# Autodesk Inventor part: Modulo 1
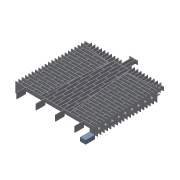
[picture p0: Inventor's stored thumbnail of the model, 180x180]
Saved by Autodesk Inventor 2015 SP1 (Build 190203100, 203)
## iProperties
Created: 2015-04
Part Number: Modulo 1
Material: Generic
Document SubType Name: Modeling
Designer: treina2
Density: 1 g/cm^3
Appearance: Default
Author: treina2
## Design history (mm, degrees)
sketch "Sketch1"
  geometry: L1 (1091.806, 200)-(1091.806, 440) reference; L2 (1091.806, 440)-(1033.806, 440) reference; L3 (1033.806, 440)-(1033.806, 200) reference; L4 (1033.806, 200)-(1091.806, 200) reference; L5 (1159.806, 200)-(1159.806, 315) reference; L6 (1159.806, 315)-(1101.806, 315) reference; L7 (1101.806, 315)-(1101.806, 200) reference; L8 (1101.806, 200)-(1159.806, 200) reference; L9 (1227.806, 200)-(1227.806, 440) reference; L10 (1227.806, 440)-(1169.806, 440) reference; L11 (1169.806, 440)-(1169.806, 200) reference; L12 (1169.806, 200)-(1227.806, 200) reference; L13 (1024, 200)-(1024, 315) reference; L14 (1024, 315)-(966, 315) reference; L15 (966, 315)-(966, 200) reference; L16 (966, 200)-(1024, 200) reference; L17 (1169.806, 1464.632)-(1169.806, 1450) reference; L18 (1169.806, 1450)-(1171.263, 1450) reference; L19 (1284.348, 315)-(1237.806, 315) reference; L20 (1237.806, 315)-(1237.806, 200) reference; L21 (1237.806, 200)-(1295.806, 200) reference; L22 (1259.439, 565)-(1283.351, 325) reference; L23 (1259.439, 565)-(1237.806, 565) reference; L24 (1237.806, 565)-(1237.806, 325) reference; L25 (1237.806, 325)-(1283.351, 325) reference; L26 (1169.806, 1565)-(1177.128, 1492) reference; L27 (1237.806, 1498.938)-(1295.806, 1505.57) reference; L28 (1295.806, 1505.57)-(1295.806, 1686) reference; L29 (1295.806, 1686)-(1237.806, 1686) reference; L30 (1237.806, 1686)-(1237.806, 1498.938) reference; L31 (1159.806, 325)-(1159.806, 565) reference; L32 (1159.806, 565)-(1101.806, 565) reference; L33 (1101.806, 565)-(1101.806, 325) reference; L34 (1101.806, 325)-(1159.806, 325) reference; L35 (1703.806, 1552.224)-(1703.806, 1686) reference; L36 (1703.806, 1686)-(1645.806, 1686) reference; L37 (1645.806, 1686)-(1645.806, 1545.592) reference; L38 (1024, 325)-(1024, 565) reference; L39 (1024, 565)-(966, 565) reference; L40 (966, 565)-(966, 325) reference; L41 (966, 325)-(1024, 325) reference; L42 (1091.806, 450)-(1091.806, 690) reference; L43 (1091.806, 690)-(1033.806, 690) reference; L44 (1033.806, 690)-(1033.806, 450) reference; L45 (1033.806, 450)-(1091.806, 450) reference; L46 (1227.806, 450)-(1227.806, 690) reference; L47 (1227.806, 690)-(1169.806, 690) reference; L48 (1169.806, 690)-(1169.806, 450) reference; L49 (1169.806, 450)-(1227.806, 450) reference; L50 (1159.806, 575)-(1159.806, 815) reference; L51 (1159.806, 815)-(1101.806, 815) reference; L52 (1101.806, 815)-(1101.806, 575) reference; L53 (1101.806, 575)-(1159.806, 575) reference; L54 (1237.806, 782.132)-(1237.806, 575) reference; L55 (1237.806, 575)-(1258.443, 575) reference; L56 (1024, 575)-(1024, 815) reference; L57 (1024, 815)-(966, 815) reference; L58 (966, 815)-(966, 575) reference; L59 (966, 575)-(1024, 575) reference; L60 (1091.806, 700)-(1091.806, 940) reference; L61 (1091.806, 940)-(1033.806, 940) reference; L62 (1033.806, 940)-(1033.806, 700) reference; L63 (1033.806, 700)-(1091.806, 700) reference; L64 (1227.806, 700)-(1227.806, 882.5) reference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; 1 further point
  constraints: 1754 end point, 397 horizontal, 367 vertical, 18 point on line, 953 other
workplane "Work Plane1"
sketch "Sketch2"
  geometry: L1 (1990, 0)-(1600, 0) reference; L2 (1990, 0)-(1880.303, 190) reference; L3 (1765, 190)-(1880.303, 190) reference; L4 (1600, 190)-(1880.303, 190) reference; L5 (1600, 0)-(1600, 190) reference; L6 (1590, 190)-(1590, 0) reference; L7 (1200, 190)-(1590, 190) reference; L8 (1590, 0)-(1200, 0) reference; L9 (1200, 0)-(1200, 190) reference; L10 (1190, 190)-(1190, 0) reference; L11 (1190, 0)-(800, 0) reference; L12 (800, 190)-(1190, 190) reference; L13 (800, 0)-(800, 190) reference; L14 (790, 190)-(790, 0) reference; L15 (400, 190)-(790, 190) reference; L16 (790, 0)-(400, 0) reference; L17 (400, 0)-(400, 190) reference; L18 (390, 190)-(390, 0) reference; L19 (109.697, 190)-(390, 190) reference; L20 (390, 0)-(0, 0) reference; L21 (0, 0)-(109.697, 190) reference; 1 further point
extrude "Extrusion1" new body sketch "Sketch2" distance "d2" = 140 (= BLOCO_PADRAO_LARG); taper "d3" = 0 deg
extrude "Extrusion2" new body sketch "Sketch2" distance "d4" = 140 (= BLOCO_PADRAO_LARG); taper "d5" = 0 deg
extrude "Extrusion3" new body sketch "Sketch2" distance "d6" = 140 (= BLOCO_PADRAO_LARG); taper "d7" = 0 deg
extrude "Extrusion4" new body sketch "Sketch2" distance "d8" = 140 (= BLOCO_PADRAO_LARG); taper "d9" = 0 deg
extrude "Extrusion5" new body sketch "Sketch2" distance "d10" = 140 (= BLOCO_PADRAO_LARG); taper "d11" = 0 deg
extrude "Extrusion6" new body sketch "Sketch1" distance "d12" = 240 (= TIJOLO_PADRAO_COMP); taper "d13" = 0 deg
extrude "Extrusion7" new body sketch "Sketch1" distance "d14" = 240 (= TIJOLO_PADRAO_COMP); taper "d15" = 0 deg
extrude "Extrusion8" new body sketch "Sketch1" distance "d16" = 115 (= TIJOLO_PADRAO_LARG); taper "d17" = 0 deg
extrude "Extrusion9" new body sketch "Sketch1" distance "d18" = 115 (= TIJOLO_PADRAO_LARG); taper "d19" = 0 deg
extrude "Extrusion10" new body sketch "Sketch1" distance "d20" = 115 (= TIJOLO_PADRAO_LARG); taper "d21" = 0 deg
extrude "Extrusion11" new body sketch "Sketch1" distance "d22" = 115 (= TIJOLO_PADRAO_LARG); taper "d23" = 0 deg
extrude "Extrusion12" new body sketch "Sketch1" distance "d24" = 115 (= TIJOLO_PADRAO_LARG); taper "d25" = 0 deg
extrude "Extrusion13" new body sketch "Sketch1" distance "d26" = 240 (= TIJOLO_PADRAO_COMP); taper "d27" = 0 deg
extrude "Extrusion14" new body sketch "Sketch1" distance "d28" = 115 (= TIJOLO_PADRAO_LARG); taper "d29" = 0 deg
extrude "Extrusion15" new body sketch "Sketch1" distance "d30" = 115 (= TIJOLO_PADRAO_LARG); taper "d31" = 0 deg
extrude "Extrusion16" new body sketch "Sketch1" distance "d32" = 115 (= TIJOLO_PADRAO_LARG); taper "d33" = 0 deg
extrude "Extrusion17" new body sketch "Sketch1" distance "d34" = 115 (= TIJOLO_PADRAO_LARG); taper "d35" = 0 deg
extrude "Extrusion18" new body sketch "Sketch1" distance "d36" = 115 (= TIJOLO_PADRAO_LARG); taper "d37" = 0 deg
extrude "Extrusion19" new body sketch "Sketch1" distance "d38" = 115 (= TIJOLO_PADRAO_LARG); taper "d39" = 0 deg
extrude "Extrusion20" new body sketch "Sketch1" distance "d40" = 115 (= TIJOLO_PADRAO_LARG); taper "d41" = 0 deg
extrude "Extrusion21" new body sketch "Sketch1" distance "d42" = 115 (= TIJOLO_PADRAO_LARG); taper "d43" = 0 deg
extrude "Extrusion22" new body sketch "Sketch1" distance "d44" = 115 (= TIJOLO_PADRAO_LARG); taper "d45" = 0 deg
extrude "Extrusion23" new body sketch "Sketch1" distance "d46" = 115 (= TIJOLO_PADRAO_LARG); taper "d47" = 0 deg
extrude "Extrusion24" new body sketch "Sketch1" distance "d48" = 240 (= TIJOLO_PADRAO_COMP); taper "d49" = 0 deg
extrude "Extrusion25" new body sketch "Sketch1" distance "d50" = 115 (= TIJOLO_PADRAO_LARG); taper "d51" = 0 deg
extrude "Extrusion26" new body sketch "Sketch1" distance "d52" = 115 (= TIJOLO_PADRAO_LARG); taper "d53" = 0 deg
extrude "Extrusion27" new body sketch "Sketch1" distance "d54" = 240 (= TIJOLO_PADRAO_COMP); taper "d55" = 0 deg
extrude "Extrusion28" new body sketch "Sketch1" distance "d56" = 115 (= TIJOLO_PADRAO_LARG); taper "d57" = 0 deg
extrude "Extrusion29" new body sketch "Sketch1" distance "d58" = 115 (= TIJOLO_PADRAO_LARG); taper "d59" = 0 deg
extrude "Extrusion30" new body sketch "Sketch1" distance "d60" = 115 (= TIJOLO_PADRAO_LARG); taper "d61" = 0 deg
extrude "Extrusion31" new body sketch "Sketch1" distance "d62" = 115 (= TIJOLO_PADRAO_LARG); taper "d63" = 0 deg
extrude "Extrusion32" new body sketch "Sketch1" distance "d64" = 115 (= TIJOLO_PADRAO_LARG); taper "d65" = 0 deg
extrude "Extrusion33" new body sketch "Sketch1" distance "d66" = 115 (= TIJOLO_PADRAO_LARG); taper "d67" = 0 deg
extrude "Extrusion34" new body sketch "Sketch1" distance "d68" = 115 (= TIJOLO_PADRAO_LARG); taper "d69" = 0 deg
extrude "Extrusion35" new body sketch "Sketch1" distance "d70" = 115 (= TIJOLO_PADRAO_LARG); taper "d71" = 0 deg
extrude "Extrusion36" new body sketch "Sketch1" distance "d72" = 240 (= TIJOLO_PADRAO_COMP); taper "d73" = 0 deg
extrude "Extrusion37" new body sketch "Sketch1" distance "d74" = 115 (= TIJOLO_PADRAO_LARG); taper "d75" = 0 deg
extrude "Extrusion38" new body sketch "Sketch1" distance "d76" = 115 (= TIJOLO_PADRAO_LARG); taper "d77" = 0 deg
extrude "Extrusion39" new body sketch "Sketch1" distance "d78" = 115 (= TIJOLO_PADRAO_LARG); taper "d79" = 0 deg
extrude "Extrusion40" new body sketch "Sketch1" distance "d80" = 115 (= TIJOLO_PADRAO_LARG); taper "d81" = 0 deg
extrude "Extrusion41" new body sketch "Sketch1" distance "d82" = 115 (= TIJOLO_PADRAO_LARG); taper "d83" = 0 deg
extrude "Extrusion42" new body sketch "Sketch1" distance "d84" = 115 (= TIJOLO_PADRAO_LARG); taper "d85" = 0 deg
extrude "Extrusion43" new body sketch "Sketch1" distance "d86" = 115 (= TIJOLO_PADRAO_LARG); taper "d87" = 0 deg
extrude "Extrusion44" new body sketch "Sketch1" distance "d88" = 240 (= TIJOLO_PADRAO_COMP); taper "d89" = 0 deg
extrude "Extrusion45" new body sketch "Sketch1" distance "d90" = 240 (= TIJOLO_PADRAO_COMP); taper "d91" = 0 deg
extrude "Extrusion46" new body sketch "Sketch1" distance "d92" = 240 (= TIJOLO_PADRAO_COMP); taper "d93" = 0 deg
extrude "Extrusion47" new body sketch "Sketch1" distance "d94" = 240 (= TIJOLO_PADRAO_COMP); taper "d95" = 0 deg
extrude "Extrusion48" new body sketch "Sketch1" distance "d96" = 240 (= TIJOLO_PADRAO_COMP); taper "d97" = 0 deg
extrude "Extrusion49" new body sketch "Sketch1" distance "d98" = 115 (= TIJOLO_PADRAO_LARG); taper "d99" = 0 deg
extrude "Extrusion50" new body sketch "Sketch1" distance "d100" = 115 (= TIJOLO_PADRAO_LARG); taper "d101" = 0 deg
extrude "Extrusion51" new body sketch "Sketch1" distance "d102" = 115 (= TIJOLO_PADRAO_LARG); taper "d103" = 0 deg
extrude "Extrusion52" new body sketch "Sketch1" distance "d104" = 115 (= TIJOLO_PADRAO_LARG); taper "d105" = 0 deg
extrude "Extrusion53" new body sketch "Sketch1" distance "d106" = 115 (= TIJOLO_PADRAO_LARG); taper "d107" = 0 deg
extrude "Extrusion54" new body sketch "Sketch1" distance "d108" = 115 (= TIJOLO_PADRAO_LARG); taper "d109" = 0 deg
extrude "Extrusion55" new body sketch "Sketch1" distance "d110" = 115 (= TIJOLO_PADRAO_LARG); taper "d111" = 0 deg
extrude "Extrusion56" new body sketch "Sketch1" distance "d112" = 115 (= TIJOLO_PADRAO_LARG); taper "d113" = 0 deg
extrude "Extrusion57" new body sketch "Sketch1" distance "d114" = 115 (= TIJOLO_PADRAO_LARG); taper "d115" = 0 deg
extrude "Extrusion58" new body sketch "Sketch1" distance "d116" = 115 (= TIJOLO_PADRAO_LARG); taper "d117" = 0 deg
extrude "Extrusion59" new body sketch "Sketch1" distance "d118" = 115 (= TIJOLO_PADRAO_LARG); taper "d119" = 0 deg
extrude "Extrusion60" new body sketch "Sketch1" distance "d120" = 115 (= TIJOLO_PADRAO_LARG); taper "d121" = 0 deg
extrude "Extrusion61" new body sketch "Sketch1" distance "d122" = 115 (= TIJOLO_PADRAO_LARG); taper "d123" = 0 deg
extrude "Extrusion62" new body sketch "Sketch1" distance "d124" = 115 (= TIJOLO_PADRAO_LARG); taper "d125" = 0 deg
extrude "Extrusion63" new body sketch "Sketch1" distance "d126" = 115 (= TIJOLO_PADRAO_LARG); taper "d127" = 0 deg
extrude "Extrusion64" new body sketch "Sketch1" distance "d128" = 115 (= TIJOLO_PADRAO_LARG); taper "d129" = 0 deg
extrude "Extrusion65" new body sketch "Sketch1" distance "d130" = 115 (= TIJOLO_PADRAO_LARG); taper "d131" = 0 deg
extrude "Extrusion66" new body sketch "Sketch1" distance "d132" = 115 (= TIJOLO_PADRAO_LARG); taper "d133" = 0 deg
extrude "Extrusion67" new body sketch "Sketch1" distance "d134" = 115 (= TIJOLO_PADRAO_LARG); taper "d135" = 0 deg
extrude "Extrusion68" new body sketch "Sketch1" distance "d136" = 115 (= TIJOLO_PADRAO_LARG); taper "d137" = 0 deg
extrude "Extrusion69" new body sketch "Sketch1" distance "d138" = 240 (= TIJOLO_PADRAO_COMP); taper "d139" = 0 deg
extrude "Extrusion70" new body sketch "Sketch1" distance "d140" = 240 (= TIJOLO_PADRAO_COMP); taper "d141" = 0 deg
extrude "Extrusion71" new body sketch "Sketch1" distance "d142" = 240 (= TIJOLO_PADRAO_COMP); taper "d143" = 0 deg
extrude "Extrusion72" new body sketch "Sketch1" distance "d144" = 240 (= TIJOLO_PADRAO_COMP); taper "d145" = 0 deg
extrude "Extrusion73" new body sketch "Sketch1" distance "d146" = 240 (= TIJOLO_PADRAO_COMP); taper "d147" = 0 deg
extrude "Extrusion74" new body sketch "Sketch1" distance "d148" = 240 (= TIJOLO_PADRAO_COMP); taper "d149" = 0 deg
extrude "Extrusion75" new body sketch "Sketch1" distance "d150" = 240 (= TIJOLO_PADRAO_COMP); taper "d151" = 0 deg
extrude "Extrusion76" new body sketch "Sketch1" distance "d152" = 240 (= TIJOLO_PADRAO_COMP); taper "d153" = 0 deg
extrude "Extrusion77" new body sketch "Sketch1" distance "d154" = 240 (= TIJOLO_PADRAO_COMP); taper "d155" = 0 deg
extrude "Extrusion78" new body sketch "Sketch1" distance "d156" = 115 (= TIJOLO_PADRAO_LARG); taper "d157" = 0 deg
extrude "Extrusion79" new body sketch "Sketch1" distance "d158" = 115 (= TIJOLO_PADRAO_LARG); taper "d159" = 0 deg
extrude "Extrusion80" new body sketch "Sketch1" distance "d160" = 115 (= TIJOLO_PADRAO_LARG); taper "d161" = 0 deg
extrude "Extrusion81" new body sketch "Sketch1" distance "d162" = 115 (= TIJOLO_PADRAO_LARG); taper "d163" = 0 deg
extrude "Extrusion82" new body sketch "Sketch1" distance "d164" = 115 (= TIJOLO_PADRAO_LARG); taper "d165" = 0 deg
extrude "Extrusion83" new body sketch "Sketch1" distance "d166" = 115 (= TIJOLO_PADRAO_LARG); taper "d167" = 0 deg
extrude "Extrusion84" new body sketch "Sketch1" distance "d168" = 115 (= TIJOLO_PADRAO_LARG); taper "d169" = 0 deg
extrude "Extrusion85" new body sketch "Sketch1" distance "d170" = 115 (= TIJOLO_PADRAO_LARG); taper "d171" = 0 deg
extrude "Extrusion86" new body sketch "Sketch1" distance "d172" = 115 (= TIJOLO_PADRAO_LARG); taper "d173" = 0 deg
extrude "Extrusion87" new body sketch "Sketch1" distance "d174" = 115 (= TIJOLO_PADRAO_LARG); taper "d175" = 0 deg
extrude "Extrusion88" new body sketch "Sketch1" distance "d176" = 115 (= TIJOLO_PADRAO_LARG); taper "d177" = 0 deg
extrude "Extrusion89" new body sketch "Sketch1" distance "d178" = 115 (= TIJOLO_PADRAO_LARG); taper "d179" = 0 deg
extrude "Extrusion90" new body sketch "Sketch1" distance "d180" = 115 (= TIJOLO_PADRAO_LARG); taper "d181" = 0 deg
pattern_linear "Rectangular Pattern1" dims "d184" = 136 (= 2 x TIJOLO_PADRAO_PROF + 2 x GAP)
pattern_linear "Rectangular Pattern2" dims "d187" = 136 (= 2 x TIJOLO_PADRAO_PROF + 2 x GAP)
pattern_linear "Rectangular Pattern3" dims "d190" = 136 (= 2 x TIJOLO_PADRAO_PROF + 2 x GAP)
extrude "Extrusion91" new body sketch "Sketch1" distance "d191" = 115 (= TIJOLO_PADRAO_LARG); taper "d192" = 0 deg
extrude "Extrusion92" new body sketch "Sketch1" distance "d193" = 115 (= TIJOLO_PADRAO_LARG); taper "d194" = 0 deg
extrude "Extrusion93" new body sketch "Sketch1" distance "d195" = 115 (= TIJOLO_PADRAO_LARG); taper "d196" = 0 deg
extrude "Extrusion94" new body sketch "Sketch1" distance "d197" = 115 (= TIJOLO_PADRAO_LARG); taper "d198" = 0 deg
extrude "Extrusion95" new body sketch "Sketch1" distance "d199" = 115 (= TIJOLO_PADRAO_LARG); taper "d200" = 0 deg
extrude "Extrusion96" new body sketch "Sketch1" distance "d201" = 115 (= TIJOLO_PADRAO_LARG); taper "d202" = 0 deg
extrude "Extrusion97" new body sketch "Sketch1" distance "d203" = 115 (= TIJOLO_PADRAO_LARG); taper "d204" = 0 deg
extrude "Extrusion98" new body sketch "Sketch1" distance "d205" = 115 (= TIJOLO_PADRAO_LARG); taper "d206" = 0 deg
extrude "Extrusion99" new body sketch "Sketch1" distance "d207" = 115 (= TIJOLO_PADRAO_LARG); taper "d208" = 0 deg
extrude "Extrusion100" new body sketch "Sketch1" distance "d209" = 115 (= TIJOLO_PADRAO_LARG); taper "d210" = 0 deg
extrude "Extrusion101" new body sketch "Sketch1" distance "d211" = 115 (= TIJOLO_PADRAO_LARG); taper "d212" = 0 deg
extrude "Extrusion102" new body sketch "Sketch1" distance "d213" = 115 (= TIJOLO_PADRAO_LARG); taper "d214" = 0 deg
extrude "Extrusion103" new body sketch "Sketch1" distance "d215" = 115 (= TIJOLO_PADRAO_LARG); taper "d216" = 0 deg
extrude "Extrusion104" new body sketch "Sketch1" distance "d217" = 115 (= TIJOLO_PADRAO_LARG); taper "d218" = 0 deg
extrude "Extrusion105" new body sketch "Sketch1" distance "d219" = 115 (= TIJOLO_PADRAO_LARG); taper "d220" = 0 deg
extrude "Extrusion106" new body sketch "Sketch1" distance "d221" = 115 (= TIJOLO_PADRAO_LARG); taper "d222" = 0 deg
extrude "Extrusion107" new body sketch "Sketch1" distance "d223" = 115 (= TIJOLO_PADRAO_LARG); taper "d224" = 0 deg
extrude "Extrusion108" new body sketch "Sketch1" distance "d225" = 115 (= TIJOLO_PADRAO_LARG); taper "d226" = 0 deg
extrude "Extrusion109" new body sketch "Sketch1" distance "d227" = 240 (= TIJOLO_PADRAO_COMP); taper "d228" = 0 deg
extrude "Extrusion110" new body sketch "Sketch1" distance "d229" = 240 (= TIJOLO_PADRAO_COMP); taper "d230" = 0 deg
workplane "Work Plane2"
sketch "Sketch3"
  geometry: L1 (898.194, 1575)-(898.194, 1815) reference; L2 (898.194, 1815)-(956.194, 1815) reference; L3 (956.194, 1815)-(956.194, 1575) reference; L4 (956.194, 1575)-(898.194, 1575) reference; L5 (966, 1575)-(966, 1815) reference; L6 (1024, 1575)-(966, 1575) reference; L7 (1024, 1815)-(1024, 1575) reference; L8 (1033.806, 1575)-(1033.806, 1815) reference; L9 (1091.806, 1575)-(1033.806, 1575) reference; L10 (1091.806, 1815)-(1091.806, 1575) reference; L11 (1033.806, 1815)-(1091.806, 1815) reference; L12 (966, 1815)-(1024, 1815) reference; 1 further point
extrude "Extrusion111" new body sketch "Sketch3" distance "d232" = 115 (= AMAR_PADRAO_LARG); taper "d233" = 0 deg
extrude "Extrusion112" new body sketch "Sketch3" distance "d234" = 115 (= AMAR_PADRAO_LARG); taper "d235" = 0 deg
extrude "Extrusion113" new body sketch "Sketch3" distance "d236" = 115 (= AMAR_PADRAO_LARG); taper "d237" = 0 deg
workplane "Work Plane3"
sketch "Sketch4"
  geometry: L1 (1081.579, 1883)-(908.421, 1883) reference; L2 (898.194, 1825)-(908.421, 1883) reference; L3 (898.194, 1825)-(1091.806, 1825) reference; L4 (1091.806, 1825)-(1081.579, 1883) reference; 1 further point
extrude "Extrusion114" new body sketch "Sketch4" distance "d239" = 115 (= AMAR_PADRAO_LARG); taper "d240" = 0 deg
workplane "Work Plane4"
sketch "Sketch5"
  geometry: L1 (1091.806, 200)-(1091.806, 440) reference; L2 (1091.806, 440)-(1033.806, 440) reference; L3 (1033.806, 440)-(1033.806, 200) reference; L4 (1033.806, 200)-(1091.806, 200) reference; L5 (1159.806, 200)-(1159.806, 315) reference; L6 (1159.806, 315)-(1101.806, 315) reference; L7 (1101.806, 315)-(1101.806, 200) reference; L8 (1101.806, 200)-(1159.806, 200) reference; L9 (1227.806, 200)-(1227.806, 440) reference; L10 (1227.806, 440)-(1169.806, 440) reference; L11 (1169.806, 440)-(1169.806, 200) reference; L12 (1169.806, 200)-(1227.806, 200) reference; L13 (1024, 200)-(1024, 315) reference; L14 (1024, 315)-(966, 315) reference; L15 (966, 315)-(966, 200) reference; L16 (966, 200)-(1024, 200) reference; L17 (1169.806, 1464.632)-(1169.806, 1450) reference; L18 (1169.806, 1450)-(1171.263, 1450) reference; L19 (1284.348, 315)-(1237.806, 315) reference; L20 (1237.806, 315)-(1237.806, 200) reference; L21 (1237.806, 200)-(1295.806, 200) reference; L22 (1259.439, 565)-(1283.351, 325) reference; L23 (1259.439, 565)-(1237.806, 565) reference; L24 (1237.806, 565)-(1237.806, 325) reference; L25 (1237.806, 325)-(1283.351, 325) reference; L26 (1169.806, 1565)-(1177.128, 1492) reference; L27 (1237.806, 1498.938)-(1295.806, 1505.57) reference; L28 (1295.806, 1505.57)-(1295.806, 1686) reference; L29 (1295.806, 1686)-(1237.806, 1686) reference; L30 (1237.806, 1686)-(1237.806, 1498.938) reference; L31 (1159.806, 325)-(1159.806, 565) reference; L32 (1159.806, 565)-(1101.806, 565) reference; L33 (1101.806, 565)-(1101.806, 325) reference; L34 (1101.806, 325)-(1159.806, 325) reference; L35 (1703.806, 1552.224)-(1703.806, 1686) reference; L36 (1703.806, 1686)-(1645.806, 1686) reference; L37 (1645.806, 1686)-(1645.806, 1545.592) reference; L38 (1024, 325)-(1024, 565) reference; L39 (1024, 565)-(966, 565) reference; L40 (966, 565)-(966, 325) reference; L41 (966, 325)-(1024, 325) reference; L42 (1091.806, 450)-(1091.806, 690) reference; L43 (1091.806, 690)-(1033.806, 690) reference; L44 (1033.806, 690)-(1033.806, 450) reference; L45 (1033.806, 450)-(1091.806, 450) reference; L46 (1227.806, 450)-(1227.806, 690) reference; L47 (1227.806, 690)-(1169.806, 690) reference; L48 (1169.806, 690)-(1169.806, 450) reference; L49 (1169.806, 450)-(1227.806, 450) reference; L50 (1159.806, 575)-(1159.806, 815) reference; L51 (1159.806, 815)-(1101.806, 815) reference; L52 (1101.806, 815)-(1101.806, 575) reference; L53 (1101.806, 575)-(1159.806, 575) reference; L54 (1237.806, 782.132)-(1237.806, 575) reference; L55 (1237.806, 575)-(1258.443, 575) reference; L56 (1024, 575)-(1024, 815) reference; L57 (1024, 815)-(966, 815) reference; L58 (966, 815)-(966, 575) reference; L59 (966, 575)-(1024, 575) reference; L60 (1091.806, 700)-(1091.806, 940) reference; L61 (1091.806, 940)-(1033.806, 940) reference; L62 (1033.806, 940)-(1033.806, 700) reference; L63 (1033.806, 700)-(1091.806, 700) reference; L64 (1227.806, 700)-(1227.806, 882.5) reference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; 2 further points
  constraints: 1754 end point, 397 horizontal, 367 vertical, 18 point on line, 953 other
extrude "Extrusion115" new body sketch "Sketch5" distance "d242" = 115 (= AMAR_PADRAO_LARG); taper "d243" = 0 deg
extrude "Extrusion116" new body sketch "Sketch5" distance "d244" = 115 (= AMAR_PADRAO_LARG); taper "d245" = 0 deg
extrude "Extrusion117" new body sketch "Sketch5" distance "d246" = 115 (= AMAR_PADRAO_LARG); taper "d247" = 0 deg
extrude "Extrusion118" new body sketch "Sketch5" distance "d248" = 115 (= AMAR_PADRAO_LARG); taper "d249" = 0 deg
extrude "Extrusion119" new body sketch "Sketch5" distance "d250" = 115 (= AMAR_PADRAO_LARG); taper "d251" = 0 deg
extrude "Extrusion120" new body sketch "Sketch5" distance "d252" = 115 (= AMAR_PADRAO_LARG); taper "d253" = 0 deg
extrude "Extrusion121" new body sketch "Sketch5" distance "d254" = 115 (= AMAR_PADRAO_LARG); taper "d255" = 0 deg
extrude "Extrusion122" new body sketch "Sketch5" distance "d256" = 115 (= AMAR_PADRAO_LARG); taper "d257" = 0 deg
extrude "Extrusion123" new body sketch "Sketch5" distance "d258" = 115 (= AMAR_PADRAO_LARG); taper "d259" = 0 deg
extrude "Extrusion124" new body sketch "Sketch5" distance "d260" = 115 (= AMAR_PADRAO_LARG); taper "d261" = 0 deg
extrude "Extrusion125" new body sketch "Sketch5" distance "d262" = 115 (= AMAR_PADRAO_LARG); taper "d263" = 0 deg
extrude "Extrusion126" new body sketch "Sketch5" distance "d264" = 115 (= AMAR_PADRAO_LARG); taper "d265" = 0 deg
extrude "Extrusion127" new body sketch "Sketch5" distance "d266" = 115 (= AMAR_PADRAO_LARG); taper "d267" = 0 deg
extrude "Extrusion128" new body sketch "Sketch5" distance "d268" = 115 (= AMAR_PADRAO_LARG); taper "d269" = 0 deg
extrude "Extrusion129" new body sketch "Sketch5" distance "d270" = 115 (= AMAR_PADRAO_LARG); taper "d271" = 0 deg
extrude "Extrusion130" new body sketch "Sketch5" distance "d272" = 115 (= AMAR_PADRAO_LARG); taper "d273" = 0 deg
extrude "Extrusion131" new body sketch "Sketch5" distance "d274" = 115 (= AMAR_PADRAO_LARG); taper "d275" = 0 deg
extrude "Extrusion132" new body sketch "Sketch5" distance "d276" = 115 (= AMAR_PADRAO_LARG); taper "d277" = 0 deg
extrude "Extrusion133" new body sketch "Sketch5" distance "d278" = 115 (= AMAR_PADRAO_LARG); taper "d279" = 0 deg
extrude "Extrusion134" new body sketch "Sketch5" distance "d280" = 115 (= AMAR_PADRAO_LARG); taper "d281" = 0 deg
extrude "Extrusion135" new body sketch "Sketch5" distance "d282" = 115 (= AMAR_PADRAO_LARG); taper "d283" = 0 deg
extrude "Extrusion136" new body sketch "Sketch5" distance "d284" = 115 (= AMAR_PADRAO_LARG); taper "d285" = 0 deg
extrude "Extrusion137" new body sketch "Sketch5" distance "d286" = 115 (= AMAR_PADRAO_LARG); taper "d287" = 0 deg
extrude "Extrusion138" new body sketch "Sketch5" distance "d288" = 115 (= AMAR_PADRAO_LARG); taper "d289" = 0 deg
extrude "Extrusion139" new body sketch "Sketch5" distance "d290" = 115 (= AMAR_PADRAO_LARG); taper "d291" = 0 deg
extrude "Extrusion140" new body sketch "Sketch5" distance "d292" = 115 (= AMAR_PADRAO_LARG); taper "d293" = 0 deg
extrude "Extrusion141" new body sketch "Sketch5" distance "d294" = 115 (= AMAR_PADRAO_LARG); taper "d295" = 0 deg
extrude "Extrusion142" new body sketch "Sketch5" distance "d296" = 115 (= AMAR_PADRAO_LARG); taper "d297" = 0 deg
extrude "Extrusion143" new body sketch "Sketch5" distance "d298" = 115 (= AMAR_PADRAO_LARG); taper "d299" = 0 deg
extrude "Extrusion144" new body sketch "Sketch5" distance "d300" = 115 (= AMAR_PADRAO_LARG); taper "d301" = 0 deg
extrude "Extrusion145" new body sketch "Sketch5" distance "d302" = 115 (= AMAR_PADRAO_LARG); taper "d303" = 0 deg
extrude "Extrusion146" new body sketch "Sketch5" distance "d304" = 115 (= AMAR_PADRAO_LARG); taper "d305" = 0 deg
extrude "Extrusion147" new body sketch "Sketch5" distance "d306" = 115 (= AMAR_PADRAO_LARG); taper "d307" = 0 deg
extrude "Extrusion148" new body sketch "Sketch5" distance "d308" = 115 (= AMAR_PADRAO_LARG); taper "d309" = 0 deg
extrude "Extrusion149" new body sketch "Sketch5" distance "d310" = 115 (= AMAR_PADRAO_LARG); taper "d311" = 0 deg
extrude "Extrusion150" new body sketch "Sketch5" distance "d312" = 115 (= AMAR_PADRAO_LARG); taper "d313" = 0 deg
extrude "Extrusion151" new body sketch "Sketch5" distance "d314" = 115 (= AMAR_PADRAO_LARG); taper "d315" = 0 deg
extrude "Extrusion152" new body sketch "Sketch5" distance "d316" = 115 (= AMAR_PADRAO_LARG); taper "d317" = 0 deg
extrude "Extrusion153" new body sketch "Sketch5" distance "d318" = 115 (= AMAR_PADRAO_LARG); taper "d319" = 0 deg
extrude "Extrusion154" new body sketch "Sketch5" distance "d320" = 115 (= AMAR_PADRAO_LARG); taper "d321" = 0 deg
extrude "Extrusion155" new body sketch "Sketch5" distance "d322" = 115 (= AMAR_PADRAO_LARG); taper "d323" = 0 deg
extrude "Extrusion156" new body sketch "Sketch5" distance "d324" = 115 (= AMAR_PADRAO_LARG); taper "d325" = 0 deg
extrude "Extrusion157" new body sketch "Sketch5" distance "d326" = 115 (= AMAR_PADRAO_LARG); taper "d327" = 0 deg
extrude "Extrusion158" new body sketch "Sketch5" distance "d328" = 115 (= AMAR_PADRAO_LARG); taper "d329" = 0 deg
extrude "Extrusion159" new body sketch "Sketch5" distance "d330" = 115 (= AMAR_PADRAO_LARG); taper "d331" = 0 deg
extrude "Extrusion160" new body sketch "Sketch5" distance "d332" = 115 (= AMAR_PADRAO_LARG); taper "d333" = 0 deg
extrude "Extrusion161" new body sketch "Sketch5" distance "d334" = 115 (= AMAR_PADRAO_LARG); taper "d335" = 0 deg
extrude "Extrusion162" new body sketch "Sketch5" distance "d336" = 115 (= AMAR_PADRAO_LARG); taper "d337" = 0 deg
extrude "Extrusion163" new body sketch "Sketch5" distance "d338" = 115 (= AMAR_PADRAO_LARG); taper "d339" = 0 deg
extrude "Extrusion164" new body sketch "Sketch5" distance "d340" = 115 (= AMAR_PADRAO_LARG); taper "d341" = 0 deg
extrude "Extrusion165" new body sketch "Sketch5" distance "d342" = 115 (= AMAR_PADRAO_LARG); taper "d343" = 0 deg
extrude "Extrusion166" new body sketch "Sketch5" distance "d344" = 115 (= AMAR_PADRAO_LARG); taper "d345" = 0 deg
extrude "Extrusion167" new body sketch "Sketch5" distance "d346" = 115 (= AMAR_PADRAO_LARG); taper "d347" = 0 deg
extrude "Extrusion168" new body sketch "Sketch5" distance "d348" = 115 (= AMAR_PADRAO_LARG); taper "d349" = 0 deg
extrude "Extrusion169" new body sketch "Sketch5" distance "d350" = 115 (= AMAR_PADRAO_LARG); taper "d351" = 0 deg
extrude "Extrusion170" new body sketch "Sketch5" distance "d352" = 115 (= AMAR_PADRAO_LARG); taper "d353" = 0 deg
extrude "Extrusion171" new body sketch "Sketch5" distance "d354" = 115 (= AMAR_PADRAO_LARG); taper "d355" = 0 deg
extrude "Extrusion172" new body sketch "Sketch5" distance "d356" = 115 (= AMAR_PADRAO_LARG); taper "d357" = 0 deg
extrude "Extrusion173" new body sketch "Sketch5" distance "d358" = 115 (= AMAR_PADRAO_LARG); taper "d359" = 0 deg
extrude "Extrusion174" new body sketch "Sketch5" distance "d360" = 115 (= AMAR_PADRAO_LARG); taper "d361" = 0 deg
extrude "Extrusion175" new body sketch "Sketch5" distance "d362" = 115 (= AMAR_PADRAO_LARG); taper "d363" = 0 deg
extrude "Extrusion176" new body sketch "Sketch5" distance "d364" = 115 (= AMAR_PADRAO_LARG); taper "d365" = 0 deg
extrude "Extrusion177" new body sketch "Sketch5" distance "d366" = 115 (= AMAR_PADRAO_LARG); taper "d367" = 0 deg
extrude "Extrusion178" new body sketch "Sketch5" distance "d368" = 115 (= AMAR_PADRAO_LARG); taper "d369" = 0 deg
extrude "Extrusion179" new body sketch "Sketch5" distance "d370" = 115 (= AMAR_PADRAO_LARG); taper "d371" = 0 deg
extrude "Extrusion180" new body sketch "Sketch5" distance "d372" = 115 (= AMAR_PADRAO_LARG); taper "d373" = 0 deg
extrude "Extrusion181" new body sketch "Sketch5" distance "d374" = 115 (= AMAR_PADRAO_LARG); taper "d375" = 0 deg
extrude "Extrusion182" new body sketch "Sketch5" distance "d376" = 115 (= AMAR_PADRAO_LARG); taper "d377" = 0 deg
workplane "Work Plane5"
sketch "Sketch6"
  geometry: L1 (-167.194, 1492)-(-282.194, 1492); L2 (-282.194, 1492)-(-282.194, 1550); L3 (-282.194, 1550)-(-167.194, 1550); L4 (-167.194, 1550)-(-167.194, 1492); 1 further point
  constraints: 8 end point, 2 parallel, 1 horizontal, 1 perpendicular
  dimensions: "d379" = 58 distance of L3.end L1.start (= TIJOLO_PADRAO_PROF); "d380" = 115 distance of L1.start L1.end (= TIJOLO_PADRAO_LARG)
extrude "Extrusion183" new body sketch "Sketch6" distance "d381" = 115 (= AMAR_PADRAO_LARG); taper "d382" = 0 deg
pattern_linear "Rectangular Pattern4" dims "d385" = 136 (= 2 x TIJOLO_PADRAO_PROF + 2 x GAP)
sketch "Sketch7"
  geometry: L1 (-1822.806, 1492)-(-1707.806, 1492); L2 (-1707.806, 1492)-(-1707.806, 1550); L3 (-1707.806, 1550)-(-1822.806, 1550); L4 (-1822.806, 1550)-(-1822.806, 1492); 1 further point
  constraints: 8 end point, 2 parallel, 1 horizontal, 1 perpendicular
  dimensions: "d386" = 115 distance of L2.end L3.end (= TIJOLO_PADRAO_LARG); "d387" = 58 distance of L3.end L1.start (= TIJOLO_PADRAO_PROF)
extrude "Extrusion184" new body sketch "Sketch7" distance "d388" = 115 (= AMAR_PADRAO_LARG); taper "d389" = 0 deg
pattern_linear "Rectangular Pattern5" dims "d392" = 136 (= 2 x TIJOLO_PADRAO_PROF + 2 x GAP)
workplane "Work Plane6"
sketch "Sketch8"
  geometry: L1 (0, 0)-(0, -240) reference; L2 (115, -240)-(0, -240); L3 (0, -240)-(0, -160); L4 (0, -160)-(115, -160); L5 (115, -160)-(115, -240); L6 (222.806, -150)-(-167.194, -150) reference; 1 further point
  constraints: 8 end point, 2 parallel, 1 horizontal, 1 perpendicular, 1 point on line
  dimensions: "d394" = 10 distance between parallel lines of L6 L4
extrude "Extrusion185" new body sketch "Sketch8" stored distance "d395" = 115 (= AMAR_PADRAO_LARG); taper "d396" = 0 deg
sketch "Sketch9"
  geometry: L1 (1540.611, 0)-(1540.611, -240) reference; L2 (1655.611, -240)-(1540.611, -240); L3 (1540.611, -240)-(1540.611, -160); L4 (1540.611, -160)-(1655.611, -160); L5 (1655.611, -160)-(1655.611, -240); L6 (1822.806, -150)-(1432.806, -150) reference; 1 further point
  constraints: 8 end point, 2 parallel, 1 horizontal, 1 perpendicular, 1 point on line
  dimensions: "d397" = 10 distance between parallel lines of L6 L4
extrude "Extrusion186" new body sketch "Sketch9" stored distance "d398" = 115 (= AMAR_PADRAO_LARG); taper "d399" = 0 deg
sketch "Sketch10"
  geometry: L1 (-10, 0)-(-400, 0) reference; L2 (-10, -140)-(-400, -140) reference; L3 (-1050, -10)-(640, -10); L4 (640, -10)-(640, -130); L5 (640, -130)-(-1050, -130); L6 (-1050, -130)-(-1050, -10); L7 (-1200, 0)-(-1200, -140) reference; L8 (790, 0)-(790, -140) reference; 1 further point
  constraints: 8 end point, 2 parallel, 1 horizontal, 1 perpendicular
  dimensions: "d400" = 10 distance between parallel lines of L1 L3; "d401" = 10 distance between parallel lines of L5 L2 (= d400); "d402" = 150 distance between parallel lines of L8 L4; "d403" = 150 distance between parallel lines of L7 L6 (= d402)
extrude "Extrusion187" new body sketch "Sketch10" distance "d404" = 190; taper "d405" = 0 deg
sketch "Sketch11"
  geometry: L1 (105.855, -10)-(247.806, -10) reference; L2 (-108.194, 95)-(-166.194, 95) reference; L3 (612.806, 10)-(-1022.806, 10); L4 (-1022.806, 10)-(-1022.806, 85); L5 (-1022.806, 85)-(612.806, 85); L6 (612.806, 85)-(612.806, 10); L7 (390, 0)-(0, 0) reference; L8 (622.806, -10)-(622.806, 230) reference; L9 (-1032.806, -10)-(-1032.806, 230) reference; 1 further point
  constraints: 8 end point, 2 parallel, 1 horizontal, 1 perpendicular
  dimensions: "d406" = 10 distance between parallel lines of L7 L3; "d407" = 10 distance between parallel lines of L2 L5 (= d406); "d408" = 10 distance between parallel lines of L9 L4 (= d406); "d409" = 10 distance between parallel lines of L8 L6 (= d406)
extrude "Extrusion188" join sketch "Sketch11" distance "d410" = 1481; taper "d411" = 0 deg
sketch "Sketch12"
  geometry: L1 (-108.194, -5)-(-108.194, 110) reference; L2 (-301.806, -5)-(-301.806, 110) reference; L3 (612.806, 85)-(-1022.806, 85) reference; L4 (-1022.806, 10)-(612.806, 10) reference; L5 (-1050, 10)-(640, 10) reference; L6 (-118.194, 10)-(-291.806, 10); L7 (-291.806, 10)-(-291.806, 85); L8 (-291.806, 85)-(-118.194, 85); L9 (-118.194, 85)-(-118.194, 10); 1 further point
  constraints: 8 end point, 2 parallel, 2 point on line, 1 horizontal, 1 perpendicular
  dimensions: "d412" = 10 distance between parallel lines of L7 L2; "d413" = 10 distance between parallel lines of L1 L9 (= d412)
extrude "Extrusion189" join sketch "Sketch12" distance "d414" = 155; taper "d415" = 0 deg
sketch "Sketch13"
  geometry: L1 (105, 1360)-(-10, 1360) reference; L2 (105, 1302)-(105, 1360) reference; L3 (-10, 1360)-(-10, 1302) reference; L4 (1645.611, 1360)-(1530.611, 1360) reference; L5 (1645.611, 1302)-(1645.611, 1360) reference; L6 (1530.611, 1360)-(1530.611, 1302) reference; L7 (0, 0)-(0, 1481) reference; L8 (1635.611, 0)-(1635.611, 1481) reference; L9 (0, 0)-(95, 0); L10 (95, 0)-(95, 1360); L11 (95, 1360)-(0, 1360); L12 (0, 1360)-(0, 0); L13 (1635.611, 0)-(1540.611, 0); L14 (1540.611, 0)-(1540.611, 1360); L15 (1540.611, 1360)-(1635.611, 1360); L16 (1635.611, 1360)-(1635.611, 0); 1 further point
  constraints: 16 end point, 4 parallel, 2 horizontal, 2 perpendicular, 2 point on line
  dimensions: "d416" = 10 distance between parallel lines of L14 L6; "d417" = 10 distance between parallel lines of L2 L10 (= d416)
extrude "Extrusion190" join sketch "Sketch13" distance "d418" = 140; taper "d419" = 0 deg
combine "Combine1"
  node "M1.1"
  node "M1.2"
  node "M1.3"
  node "M1.4"
  node "M1.5"
  node "M1.6"
  node "M1.7"
  node "M1.8"
  node "M1.9"
  node "M1.10"
  node "M1.11"
  node "M1.12"
  node "M1.13"
  node "M1.14"
  node "M1.15"
  node "M1.16"
  node "M1.17"
  node "M1.18"
  node "M1.19"
  node "M1.20"
  node "M1.21"
  node "M1.22"
  node "M1.23"
  node "M1.24"
  node "M1.25"
  node "M1.26"
  node "M1.27"
  node "M1.28"
  node "M1.29"
  node "M1.30"
  node "M1.31"
  node "M1.32"
  node "M1.33"
  node "M1.34"
  node "M1.35"
  node "M1.36"
  node "M1.37"
  node "M1.38"
  node "M1.39"
  node "M1.40"
  node "M1.41"
  node "M1.42"
  node "M1.43"
  node "M1.44"
  node "M1.45"
  node "M1.46"
  node "M1.47"
  node "M1.48"
  node "M1.49"
  node "M1.50"
  node "M1.51"
  node "M1.52"
  node "M1.53"
  node "M1.54"
  node "M1.55"
  node "M1.56"
  node "M1.57"
  node "M1.58"
  node "M1.59"
  node "M1.60"
  node "M1.61"
  node "M1.62"
  node "M1.63"
  node "M1.64"
  node "M1.65"
  node "M1.66"
  node "M1.67"
  node "M1.68"
  node "M1.69"
  node "M1.70"
  node "M1.71"
  node "M1.72"
  node "M1.73"
  node "M1.74"
  node "M1.75"
  node "M1.76"
  node "M1.77"
  node "M1.78"
  node "M1.79"
  node "M1.80"
  node "M1.81"
  node "M1.82"
  node "M1.83"
  node "M1.84"
  node "M1.85"
  node "M1.86"
  node "M1.87"
  node "M1.88"
  node "M1.89"
  node "M1.90"
  node "M1.91"
  node "M1.92"
  node "M1.93"
  node "M1.94"
  node "M1.95"
  node "M1.96"
  node "M1.97"
  node "M1.98"
  node "M1.99"
  node "M1.100"
  node "M1.101"
  node "M1.102"
  node "M1.103"
  node "M1.104"
  node "M1.105"
  node "M1.106"
  node "M1.107"
  node "M1.108"
  node "M1.109"
  node "M1.110"
  node "M1.111"
  node "M1.112"
  node "M1.113"
  node "M1.114"
  node "M1.115"
  node "M1.116"
  node "M1.117"
  node "M1.118"
  node "M1.119"
  node "M1.120"
  node "M1.121"
  node "M1.122"
  node "M1.123"
  node "M1.124"
  node "M1.125"
  node "M1.126"
  node "M1.127"
  node "M1.128"
  node "M1.129"
  node "M1.130"
  node "M1.131"
  node "M1.132"
  node "M1.133"
  node "M1.134"
  node "M1.135"
  node "M1.136"
  node "M1.137"
  node "M1.138"
  node "M1.139"
  node "M1.140"
  node "M1.141"
  node "M1.142"
  node "M1.143"
  node "M1.144"
  node "M1.145"
  node "M1.146"
  node "M1.147"
  node "M1.148"
  node "M1.149"
  node "M1.150"
  node "M1.151"
  node "M1.152"
  node "M1.153"
  node "M1.154"
  node "M1.155"
  node "M1.156"
  node "M1.157"
  node "M1.158"
  node "M1.159"
  node "M1.160"
  node "M1.161"
  node "M1.162"
  node "M1.163"
  node "M1.164"
  node "M1.165"
  node "M1.166"
  node "M1.167"
  node "M1.168"
  node "M1.169"
  node "M1.170"
  node "M1.171"
  node "M1.172"
  node "M1.173"
  node "M1.174"
  node "M1.175"
  node "M1.176"
  node "M1.177"
  node "M1.178"
  node "M1.179"
  node "M1.180"
  node "M1.181"
  node "M1.182"
  node "M1.183"
  node "M1.184"
  node "M1.185"
  node "M1.186"
  node "M1.187"
  node "M1.188"
  node "M1.189"
  node "M1.190"
  node "M1.191"
  node "M1.192"
  node "M1.193"
  node "M1.194"
  node "M1.195"
  node "M1.196"
  node "M1.197"
  node "M1.198"
  node "M1.199"
  node "M1.200"
  node "M1.201"
  node "M1.202"
  node "M1.203"
  node "M1.204"
  node "M1.205"
  node "M1.206"
  node "M1.207"
  node "M1.208"
  node "M1.209"
  node "M1.210"
  node "M1.211"
  node "M1.212"
  node "M1.213"
  node "M1.214"
  node "M1.215"
  node "M1.216"
  node "M1.217"
  node "M1.218"
  node "M1.219"
  node "M1.220"
  node "M1.221"
  node "M1.222"
  node "M1.223"
  node "M1.224"
feature "Pattern of M1.90:1"
feature "Pattern of M1.90:2"
feature "Pattern of M1.90:3"
feature "Pattern of M1.90:4"
feature "Pattern of M1.90:5"
feature "Pattern of M1.90:6"
feature "Pattern of M1.90:7"
feature "Pattern of M1.90:8"
feature "Pattern of M1.90:9"
feature "Pattern of M1.90:10"
feature "Pattern of M1.90:11"
feature "Pattern of M1.90:12"
feature "Pattern of M1.90:13"
feature "Pattern of M1.90:14"
feature "Pattern of M1.90:15"
feature "Pattern of M1.90:16"
feature "Pattern of M1.90:17"
feature "Pattern of M1.90:18"
feature "Pattern of M1.90:19"
feature "Pattern of M1.90:20"
feature "Pattern of M1.90:21"
feature "Pattern of M1.204:22"
feature "Pattern of M1.204:23"
feature "Pattern of M1.204:24"
feature "Pattern of M1.204:25"
feature "Pattern of M1.204:26"
feature "Pattern of M1.204:27"
feature "Pattern of M1.204:28"
feature "Pattern of M1.204:29"
feature "Pattern of M1.204:30"
feature "Pattern of M1.214:31"
feature "Pattern of M1.214:32"
feature "Pattern of M1.214:33"
feature "Pattern of M1.214:34"
feature "Pattern of M1.214:35"
feature "Pattern of M1.214:36"
feature "Pattern of M1.214:37"
feature "Pattern of M1.214:38"
feature "Pattern of M1.214:39"
node "M1.225"
node "Cimento"
other parameters: "TIJOLO_PADRAO_COMP" = 240 [user parameter; used in 22 equation terms], "TIJOLO_PADRAO_LARG" = 115 [user parameter; used in 85 equation terms], "TIJOLO_PADRAO_PROF" = 58 [user parameter; used in 7 equation terms], "BLOCO_PADRAO_LARG" = 140 [user parameter; used in 5 equation terms], "AMAR_PADRAO_LARG" = 115 [user parameter; used in 76 equation terms], "AMAR_PADRAO_PROF" = 58 [user parameter], "d231" = -5, "d238" = 15
